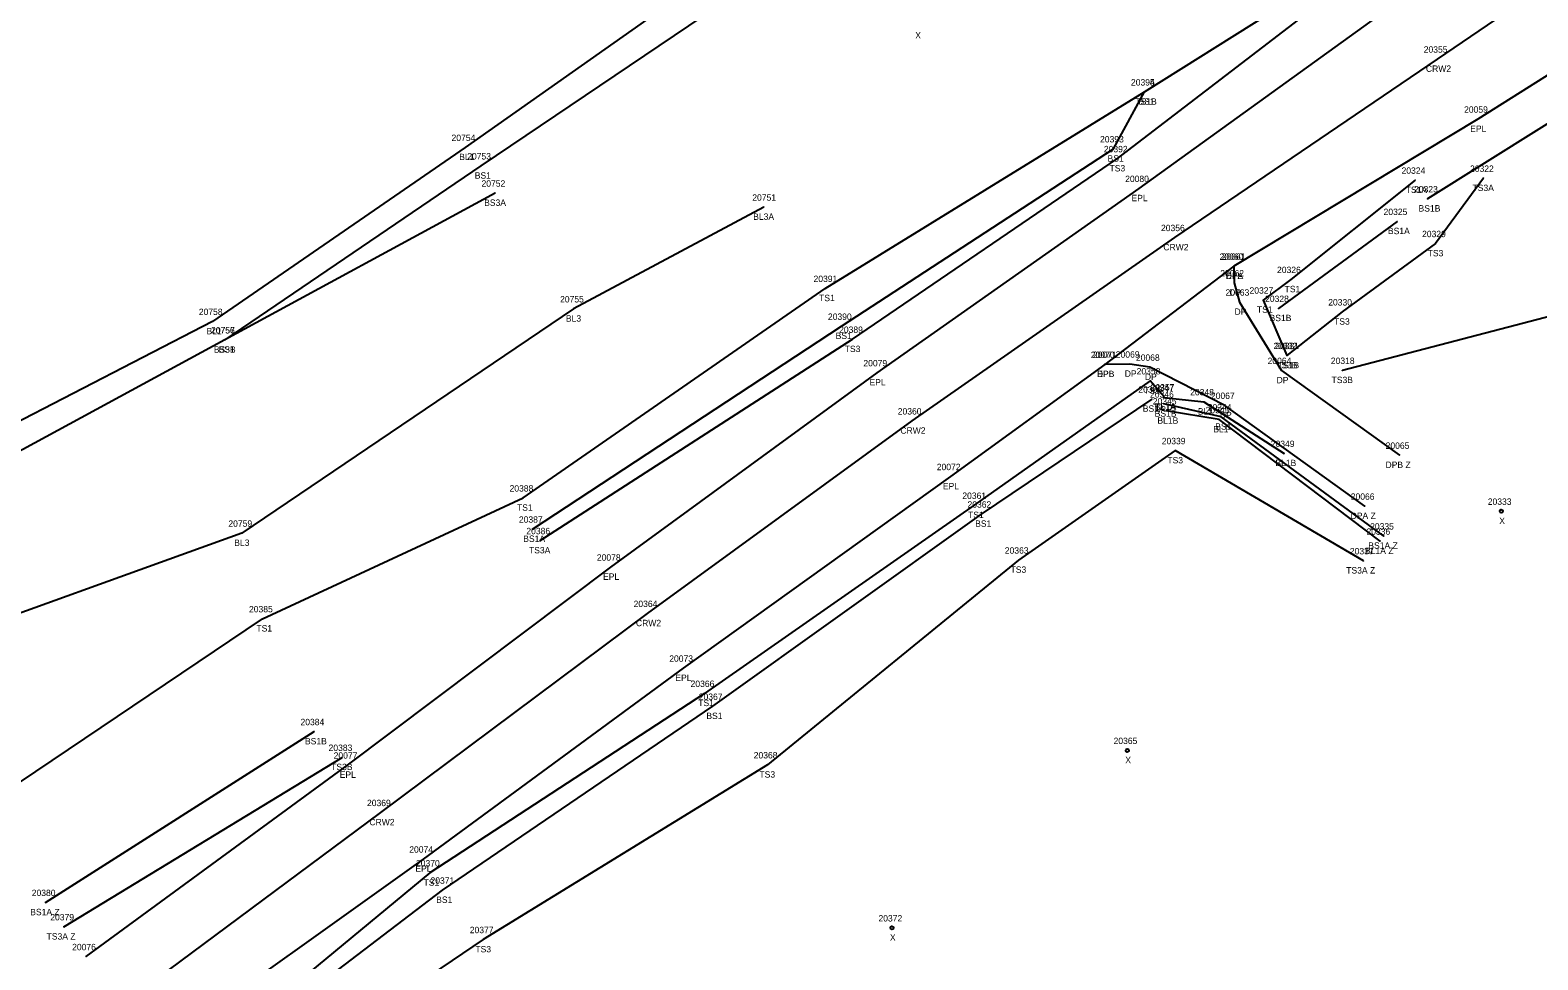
# Model space of a CAD drawing. Extents: x 1813127 to 1818290, y 1178171 to 1179900.
# Drawn here: x 1813568.5 to 1813804.5, y 1178473.8 to 1178619.3 of the extents above; entities that cross this region are included whole.
import ezdxf

# ---------------------------------------------------------------- set-up
doc = ezdxf.new("R2010")
doc.units = 0
for name, color, linetype in [('RD_DTM_BkLn1', 7, 'Continuous'), ('RD_DTM_BkLn2', 7, 'Continuous'), ('RD_EX_Driveway', 7, 'Continuous'), ('RD_EX_Driveway_txCode', 7, 'Continuous'), ('RD_EX_Road', 7, 'Continuous'), ('RD_EX_Road_txCode', 7, 'Continuous'), ('RD_SMD_Locator', 7, 'Continuous'), ('RD_SMD_Misc', 7, 'Continuous')]:
    doc.layers.add(name, color=color, linetype=linetype)

msp = doc.modelspace()

# ---------------------------------------------------------------- linework, layer by layer
at = {"layer": 'RD_DTM_BkLn1'}
for points in [[(1813684.91, 1178649.24), (1813672.9, 1178626.57), (1813636.59, 1178600.97), (1813597.02, 1178573.71), (1813553.38, 1178551.14), (1813526.62, 1178527.89)], [(1813831.28, 1178643.33), (1813821.11, 1178637.41), (1813809.78, 1178629.12), (1813788.78, 1178614.79), (1813747.67, 1178586.85), (1813706.5, 1178558.14), (1813665.11, 1178528), (1813623.37, 1178496.83), (1813582.75, 1178466.66)], [(1813683.38, 1178591.62), (1813653.58, 1178575.69), (1813601.65, 1178540.57), (1813550.07, 1178522.01), (1813545.91, 1178506.15)], [(1813745.95, 1178561.82), (1813752.22, 1178561.14), (1813764.83, 1178553.06)], [(1813779.84, 1178539.31), (1813754.64, 1178558.34), (1813746.36, 1178559.71)]]:
    msp.add_lwpolyline(points, dxfattribs=at)
at = {"layer": 'RD_DTM_BkLn2'}
for p, q in [((1813641.28, 1178593.81), (1813598.95, 1178570.83)), ((1813782.5, 1178589.38), (1813763.95, 1178575.76)), ((1813570.91, 1178482.75), (1813612.94, 1178509.5)), ((1813573.76, 1178478.94), (1813617.33, 1178505.47))]:
    msp.add_line(p, q, dxfattribs=at)
for points in [[(1813648.32, 1178539.4), (1813697.26, 1178570.92), (1813738.71, 1178599.2), (1813778.43, 1178629.72), (1813788.89, 1178635.21), (1813789.75, 1178645.61), (1813795.55, 1178639.4), (1813796.73, 1178649.77), (1813786.93, 1178659.75), (1813776.01, 1178666.91), (1813768.6, 1178671.47), (1813763.23, 1178675.13), (1813760.53, 1178679.87)], [(1813647.13, 1178541.2), (1813695.54, 1178572.96), (1813738.1, 1178600.74), (1813742.95, 1178609.65), (1813776.97, 1178631.04), (1813783.78, 1178636.69), (1813785.55, 1178637.95), (1813783.65, 1178657.07), (1813774.21, 1178663.42), (1813755.25, 1178670.65), (1813744.09, 1178675.31)], [(1813687.73, 1178647.6), (1813673.94, 1178621.63), (1813639.04, 1178598.07), (1813598.95, 1178570.83), (1813556.33, 1178547.73), (1813528.18, 1178524.13)], [(1814014.78, 1178443.42), (1813981.68, 1178475.25), (1813945.25, 1178510.83), (1813909.11, 1178545.75), (1813871.28, 1178580.16), (1813838.14, 1178611.58), (1813831.82, 1178617.25), (1813823.34, 1178615.53), (1813787.27, 1178592.92)], [(1813561.84, 1178498.2), (1813604.88, 1178527.17), (1813645.67, 1178546.08), (1813692.97, 1178578.89), (1813742.95, 1178609.65)], [(1813893.16, 1178338.84), (1813921.32, 1178364.43), (1813929.94, 1178352.15), (1813936.66, 1178353.94), (1813964.13, 1178381.53), (1813993.38, 1178417.59), (1814007.74, 1178441.51), (1813972.38, 1178457.8), (1813931.97, 1178507.78), (1813904.27, 1178536.29), (1813860.78, 1178571.07), (1813835.97, 1178602.37), (1813828.98, 1178599.83), (1813813.84, 1178586.1), (1813811.52, 1178575.86), (1813773.95, 1178566.06)], [(1813796.03, 1178596.13), (1813788.52, 1178585.91), (1813773.87, 1178575.21), (1813765.25, 1178568.38)], [(1813785.3, 1178595.83), (1813765.84, 1178580.29), (1813761.51, 1178577.07), (1813765.25, 1178568.38)], [(1813746.03, 1178561.9), (1813743.83, 1178564.42), (1813716.29, 1178544.93), (1813674.06, 1178515.49), (1813631.05, 1178487.38), (1813591.54, 1178454.7)], [(1813744.11, 1178561.57), (1813717.38, 1178543.56), (1813675.31, 1178513.46), (1813633, 1178484.68), (1813592.1, 1178453.49)], [(1813780.39, 1178540.13), (1813754.97, 1178558.77), (1813745.96, 1178560.8)], [(1813777.22, 1178536.25), (1813747.77, 1178553.49), (1813723.22, 1178536.36), (1813683.91, 1178504.3), (1813639.44, 1178476.94), (1813596.75, 1178448.06)]]:
    msp.add_lwpolyline(points, dxfattribs=at)
at = {"layer": 'RD_EX_Driveway'}
for points in [[(1813756.93, 1178582.36), (1813756.99, 1178579.76), (1813757.82, 1178576.75), (1813764.4, 1178566.04), (1813782.88, 1178552.77)], [(1813777.44, 1178544.79), (1813755.53, 1178560.58), (1813743.79, 1178566.55), (1813740.64, 1178567.05), (1813736.74, 1178567)]]:
    msp.add_lwpolyline(points, dxfattribs=at)
at = {"layer": 'RD_EX_Road'}
for points in [[(1813577.25, 1178474.27), (1813618.17, 1178504.26), (1813659.38, 1178535.26), (1813701.1, 1178565.69), (1813742.11, 1178594.54), (1813782.72, 1178623.8), (1813791.22, 1178630.12), (1813798.98, 1178638.62), (1813801.09, 1178645.46), (1813800.26, 1178651.57), (1813775.58, 1178673.13), (1813768.46, 1178675.91), (1813762.33, 1178681.89)], [(1813815.99, 1178618.51), (1813795.14, 1178605.39), (1813756.93, 1178582.36), (1813736.74, 1178567), (1813712.58, 1178549.43), (1813670.71, 1178519.43), (1813630, 1178489.55), (1813588.23, 1178459.7)]]:
    msp.add_lwpolyline(points, dxfattribs=at)
at = {"layer": 'RD_SMD_Locator'}
for centre, radius in [((1813788.78, 1178614.79), 0.001), ((1813742.95, 1178609.65), 0.001), ((1813742.95, 1178609.65), 0.001), ((1813795.14, 1178605.39), 0.001), ((1813636.59, 1178600.97), 0.001), ((1813738.1, 1178600.74), 0.001), ((1813738.71, 1178599.2), 0.001), ((1813639.04, 1178598.07), 0.001), ((1813796.03, 1178596.13), 0.001), ((1813641.28, 1178593.81), 0.001), ((1813742.11, 1178594.54), 0.001), ((1813785.3, 1178595.83), 0.001), ((1813683.38, 1178591.62), 0.001), ((1813787.27, 1178592.92), 0.001), ((1813782.5, 1178589.38), 0.001), ((1813747.67, 1178586.85), 0.001), ((1813788.52, 1178585.91), 0.001), ((1813756.93, 1178582.36), 0.001), ((1813756.93, 1178582.36), 0.001), ((1813756.99, 1178579.76), 0.001), ((1813765.84, 1178580.29), 0.001), ((1813692.97, 1178578.89), 0.001), ((1813761.51, 1178577.07), 0.001), ((1813653.58, 1178575.69), 0.001), ((1813757.82, 1178576.75), 0.001), ((1813763.95, 1178575.76), 0.001), ((1813773.87, 1178575.21), 0.001), ((1813597.02, 1178573.71), 0.001), ((1813695.54, 1178572.96), 0.001), ((1813598.95, 1178570.83), 0.001), ((1813598.95, 1178570.83), 0.001), ((1813697.26, 1178570.92), 0.001), ((1813765.25, 1178568.38), 0.001), ((1813765.25, 1178568.38), 0.001), ((1813701.1, 1178565.69), 0.001), ((1813736.74, 1178567), 0.001), ((1813736.74, 1178567), 0.001), ((1813740.64, 1178567.05), 0.001), ((1813743.79, 1178566.55), 0.001), ((1813764.4, 1178566.04), 0.001), ((1813773.95, 1178566.06), 0.001), ((1813743.83, 1178564.42), 0.001), ((1813744.11, 1178561.57), 0.001), ((1813745.95, 1178561.82), 0.001), ((1813745.96, 1178560.8), 0.001), ((1813746.03, 1178561.9), 0.001), ((1813752.22, 1178561.14), 0.001), ((1813755.53, 1178560.58), 0.001), ((1813706.5, 1178558.14), 0.001), ((1813746.36, 1178559.71), 0.001), ((1813754.64, 1178558.34), 0.001), ((1813754.97, 1178558.77), 0.001), ((1813747.77, 1178553.49), 0.001), ((1813764.83, 1178553.06), 0.001), ((1813782.88, 1178552.77), 0.001), ((1813712.58, 1178549.43), 0.001), ((1813645.67, 1178546.08), 0.001), ((1813716.29, 1178544.93), 0.001), ((1813777.44, 1178544.79), 0.001), ((1813798.81, 1178544), 0.25), ((1813717.38, 1178543.56), 0.001), ((1813601.65, 1178540.57), 0.001), ((1813647.13, 1178541.2), 0.001), ((1813648.32, 1178539.4), 0.001), ((1813779.84, 1178539.31), 0.001), ((1813780.39, 1178540.13), 0.001), ((1813659.38, 1178535.26), 0.001), ((1813723.22, 1178536.36), 0.001), ((1813777.22, 1178536.25), 0.001), ((1813665.11, 1178528), 0.001), ((1813604.88, 1178527.17), 0.001), ((1813670.71, 1178519.43), 0.001), ((1813674.06, 1178515.49), 0.001), ((1813675.31, 1178513.46), 0.001), ((1813612.94, 1178509.5), 0.001), ((1813740.26, 1178506.55), 0.25), ((1813617.33, 1178505.47), 0.001), ((1813618.17, 1178504.26), 0.001), ((1813683.91, 1178504.3), 0.001), ((1813623.37, 1178496.83), 0.001), ((1813630, 1178489.55), 0.001), ((1813631.05, 1178487.38), 0.001), ((1813570.91, 1178482.75), 0.001), ((1813633, 1178484.68), 0.001), ((1813573.76, 1178478.94), 0.001), ((1813703.41, 1178478.77), 0.25), ((1813639.44, 1178476.94), 0.001), ((1813577.25, 1178474.27), 0.001)]:
    msp.add_circle(centre, radius, dxfattribs=at)

# ---------------------------------------------------------------- texts
at = {"layer": 'RD_EX_Driveway_txCode'}
for s, p in [('20061', (1813755.03, 1178583.36)), ('20062', (1813754.81, 1178580.76)), ('DPA', (1813755.66, 1178580.36)), ('20063', (1813755.64, 1178577.75)), ('DP', (1813756.21, 1178577.76)), ('DP', (1813757.04, 1178574.75)), ('20070', (1813734.55, 1178568)), ('20069', (1813738.46, 1178568.05)), ('20068', (1813741.61, 1178567.55)), ('20064', (1813762.22, 1178567.04)), ('DPB', (1813735.49, 1178565)), ('DP', (1813739.86, 1178565.05)), ('DP', (1813743.01, 1178564.55)), ('DP', (1813763.63, 1178564.04)), ('20067', (1813753.35, 1178561.58)), ('DP', (1813754.75, 1178558.58)), ('20065', (1813780.7, 1178553.77)), ('DPB Z', (1813780.68, 1178550.77)), ('20066', (1813775.24, 1178545.79)), ('DPA Z', (1813775.22, 1178542.79))]:
    msp.add_text(s, height=1, dxfattribs=at).set_placement(p)
at = {"layer": 'RD_EX_Road_txCode'}
for s, p in [('20059', (1813792.98, 1178606.39)), ('EPL', (1813793.93, 1178603.39)), ('20080', (1813739.92, 1178595.54)), ('EPL', (1813740.91, 1178592.54)), ('20060', (1813754.71, 1178583.36)), ('EPL', (1813755.73, 1178580.36)), ('20079', (1813698.94, 1178566.69)), ('20071', (1813734.87, 1178568)), ('EPL', (1813735.54, 1178565)), ('EPL', (1813699.9, 1178563.69)), ('20072', (1813710.43, 1178550.43)), ('EPL', (1813711.38, 1178547.43)), ('20078', (1813657.22, 1178536.26)), ('EPL', (1813658.18, 1178533.26)), ('20073', (1813668.55, 1178520.43)), ('EPL', (1813669.5, 1178517.43)), ('20077', (1813616.01, 1178505.26)), ('EPL', (1813616.96, 1178502.26)), ('20074', (1813627.85, 1178490.55)), ('EPL', (1813628.8, 1178487.55)), ('20076', (1813575.07, 1178475.27))]:
    msp.add_text(s, height=1, dxfattribs=at).set_placement(p)
at = {"layer": 'RD_SMD_Misc'}
for s, p in [('X', (1813707.06, 1178618.02)), ('20355', (1813786.66, 1178615.79)), ('CRW2', (1813787.01, 1178612.79)), ('20394', (1813740.83, 1178610.65)), ('20395', (1813740.83, 1178610.65)), ('TS1B', (1813741.52, 1178607.65)), ('BS1', (1813742.01, 1178607.65)), ('20754', (1813634.47, 1178601.97)), ('20393', (1813735.99, 1178601.74)), ('20392', (1813736.59, 1178600.2)), ('BL1', (1813635.67, 1178598.97)), ('20753', (1813636.92, 1178599.07)), ('BS1', (1813737.16, 1178598.74)), ('TS3', (1813737.47, 1178597.2)), ('BS1', (1813638.1, 1178596.07)), ('20324', (1813783.19, 1178596.83)), ('20322', (1813793.91, 1178597.13)), ('20752', (1813639.16, 1178594.81)), ('20751', (1813681.55, 1178592.62)), ('TS1A', (1813783.85, 1178593.83)), ('20323', (1813785.15, 1178593.92)), ('TS3A', (1813794.3, 1178594.13)), ('BS3A', (1813639.57, 1178591.81)), ('20325', (1813780.38, 1178590.38)), ('BS1B', (1813785.85, 1178590.92)), ('BL3A', (1813681.69, 1178589.62)), ('20356', (1813745.53, 1178587.85)), ('BS1A', (1813781.06, 1178587.38)), ('20329', (1813786.4, 1178586.91)), ('CRW2', (1813745.9, 1178584.85)), ('TS3', (1813787.28, 1178583.91)), ('20326', (1813763.7, 1178581.29)), ('20391', (1813691.14, 1178579.89)), ('20755', (1813651.46, 1178576.69)), ('TS1', (1813692.01, 1178576.89)), ('20327', (1813759.39, 1178578.07)), ('20328', (1813761.83, 1178576.76)), ('TS1', (1813764.88, 1178578.29)), ('20330', (1813771.71, 1178576.21)), ('20758', (1813594.9, 1178574.71)), ('BL3', (1813652.37, 1178573.69)), ('20390', (1813693.39, 1178573.96)), ('TS1', (1813760.55, 1178575.07)), ('BS1B', (1813762.53, 1178573.76)), ('BL1', (1813596.1, 1178571.71)), ('20756', (1813596.8, 1178571.83)), ('20757', (1813596.83, 1178571.83)), ('20389', (1813695.14, 1178571.92)), ('TS3', (1813772.63, 1178573.21)), ('BS1', (1813694.6, 1178570.96)), ('TS3', (1813696.02, 1178568.92)), ('20332', (1813763.13, 1178569.38)), ('20331', (1813763.41, 1178569.38)), ('BS3B', (1813597.25, 1178568.83)), ('BS1', (1813598, 1178568.83)), ('20318', (1813772.12, 1178567.06)), ('20358', (1813741.72, 1178565.42)), ('TS3B', (1813763.53, 1178566.38)), ('TS1B', (1813763.82, 1178566.38)), ('20359', (1813741.99, 1178562.57)), ('TS1', (1813742.87, 1178562.42)), ('20346', (1813743.82, 1178561.8)), ('20347', (1813743.84, 1178562.82)), ('20357', (1813743.91, 1178562.9)), ('20348', (1813750.1, 1178562.14)), ('TS3B', (1813772.24, 1178564.06)), ('BS1A', (1813742.68, 1178559.57)), ('20345', (1813744.25, 1178560.71)), ('TS1A', (1813744.58, 1178559.9)), ('BL1A', (1813744.54, 1178559.82)), ('20344', (1813752.85, 1178559.77)), ('20360', (1813704.32, 1178559.14)), ('BS1B', (1813744.54, 1178558.8)), ('BL1B', (1813744.97, 1178557.71)), ('BL1', (1813751.3, 1178559.14)), ('20343', (1813752.52, 1178559.34)), ('CRW2', (1813704.73, 1178556.14)), ('BL1', (1813753.72, 1178556.34)), ('BS1', (1813754.03, 1178556.77)), ('20339', (1813745.65, 1178554.49)), ('20349', (1813762.72, 1178554.06)), ('TS3', (1813746.53, 1178551.49)), ('BL1B', (1813763.44, 1178551.06)), ('20388', (1813643.55, 1178547.08)), ('20361', (1813714.43, 1178545.93)), ('TS1', (1813644.71, 1178544.08)), ('20362', (1813715.24, 1178544.56)), ('TS1', (1813715.33, 1178542.93)), ('20333', (1813796.69, 1178545)), ('20759', (1813599.53, 1178541.57)), ('20387', (1813645.01, 1178542.2)), ('BS1', (1813716.44, 1178541.56)), ('20335', (1813778.27, 1178541.13)), ('X', (1813798.49, 1178542)), ('BL3', (1813600.45, 1178538.57)), ('BS1A', (1813645.69, 1178539.2)), ('20386', (1813646.18, 1178540.4)), ('20336', (1813777.7, 1178540.31)), ('TS3A', (1813646.59, 1178537.4)), ('20363', (1813721.08, 1178537.36)), ('20337', (1813775.1, 1178537.25)), ('BL1A Z', (1813777.47, 1178537.31)), ('BS1A Z', (1813777.99, 1178538.13)), ('TS3', (1813721.98, 1178534.36)), ('TS3A Z', (1813774.53, 1178534.25)), ('20364', (1813662.97, 1178529)), ('20385', (1813602.76, 1178528.17)), ('TS1', (1813603.92, 1178525.17)), ('CRW2', (1813663.34, 1178526)), ('20366', (1813671.89, 1178516.49)), ('TS1', (1813673.09, 1178513.49)), ('20367', (1813673.17, 1178514.46)), ('20384', (1813610.82, 1178510.5)), ('BS1', (1813674.36, 1178511.46)), ('BS1B', (1813611.52, 1178507.5)), ('20365', (1813738.11, 1178507.55)), ('20383', (1813615.22, 1178506.47)), ('20368', (1813681.77, 1178505.3)), ('TS3B', (1813615.62, 1178503.47)), ('X', (1813739.94, 1178504.55)), ('TS3', (1813682.67, 1178502.3)), ('20369', (1813621.23, 1178497.83)), ('CRW2', (1813621.61, 1178494.83)), ('20370', (1813628.9, 1178488.38)), ('TS1', (1813630.09, 1178485.38)), ('20371', (1813631.17, 1178485.68)), ('20380', (1813568.75, 1178483.75)), ('BS1', (1813632.06, 1178482.68)), ('BS1A Z', (1813568.51, 1178480.75)), ('20379', (1813571.65, 1178479.94)), ('20372', (1813701.3, 1178479.77)), ('TS3A Z', (1813571.07, 1178476.94)), ('20377', (1813637.32, 1178477.94)), ('TS3', (1813638.2, 1178474.94)), ('X', (1813703.1, 1178476.77))]:
    msp.add_text(s, height=1, dxfattribs=at).set_placement(p)

doc.saveas('drawing.dxf')
